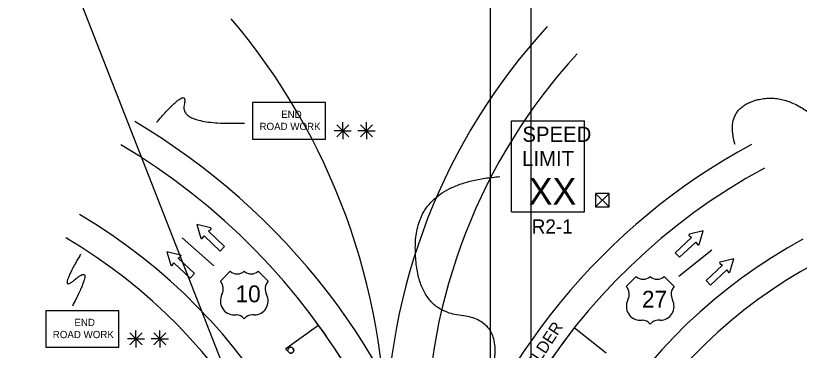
# Model space of a CAD drawing. Extents: x 16715 to 19504, y 7040 to 8495.
# Drawn here: x 16714.6 to 17178.6, y 7997.5 to 8196 of the extents above; entities that cross this region are included whole.
import ezdxf

# ---------------------------------------------------------------- set-up
doc = ezdxf.new("R2010")
doc.units = 0
for name, color, linetype in [('ALI_LEGAL_EX', 7, 'Continuous'), ('MT_SCRATCH_LEVEL_A', 7, 'Continuous'), ('MT_SCRATCH_LEVEL_E', 7, 'Continuous'), ('PAVT_EDGE_EX', 7, 'Continuous'), ('TRAFFIC_SIGNS_PR', 7, 'Continuous'), ('TYPICAL_EX', 7, 'Continuous'), ('TYPICAL_TEXT_DIMEN_PR', 7, 'Continuous')]:
    doc.layers.add(name, color=color, linetype=linetype)

msp = doc.modelspace()

# ---------------------------------------------------------------- linework, layer by layer
at = {"layer": 'ALI_LEGAL_EX'}
for p, q in [((16714.57, 8302.79), (16936.6, 7734.43)), ((16995.53, 8241.3), (16995.53, 7423.16)), ((17019.53, 8241.3), (17019.53, 7423.16))]:
    msp.add_line(p, q, dxfattribs=at)
for points in [[(16831.92, 8047.71), (16813.25, 8064.33)], [(17107.31, 8041.46), (17126.77, 8057.16)]]:
    msp.add_lwpolyline(points, dxfattribs=at)
for centre, radius, start, end in [((16545.79, 7943.78), 388, 0, 40.1908), ((17297.79, 7943.78), 364, 137.516, 180), ((17297.79, 7943.78), 340, 137.516, 180)]:
    msp.add_arc(centre, radius, start, end, dxfattribs=at)
at = {"layer": 'MT_SCRATCH_LEVEL_A'}
for points in [[(16893.99, 8012.41), (16874.52, 7998.38)], [(17064.2, 7995.96), (17045.35, 8010.82)], [(16875.01, 7997.69), (16875.7, 7997.68)]]:
    msp.add_lwpolyline(points, dxfattribs=at)
for centre, radius, start, end in [((16579.24, 7785.52), 388, 22.8554, 35.7873), ((17331.24, 7785.52), 364, 141.7598, 180), ((16579.24, 7785.52), 364, 35.6537, 35.7873), ((16877.5, 7997.65), 1.8, 0, 179.0978), ((16877.5, 7997.65), 1.8, 250.5205, 0)]:
    msp.add_arc(centre, radius, start, end, dxfattribs=at)
at = {"layer": 'MT_SCRATCH_LEVEL_E'}
for p, q in [((16829.97, 8070.13), (16821.86, 8072.1)), ((16821.86, 8072.1), (16824.29, 8064.14)), ((16825.12, 8064.02), (16826.11, 8065.52)), ((16826.11, 8065.52), (16835.74, 8056.41)), ((16828.69, 8068.24), (16830.14, 8069.32)), ((16838.31, 8059.12), (16828.69, 8068.24)), ((17113.39, 8065.58), (17114.83, 8064.5)), ((17121.65, 8068.35), (17113.56, 8066.4)), ((17119.21, 8060.38), (17121.65, 8068.35)), ((17114.83, 8064.5), (17105.16, 8055.43)), ((17107.72, 8052.7), (17117.39, 8061.77)), ((17117.39, 8061.77), (17118.38, 8060.26)), ((16812.15, 8054.06), (16804.04, 8056.02)), ((16804.04, 8056.02), (16806.47, 8048.06)), ((16835.74, 8056.41), (16838.31, 8059.12)), ((16810.87, 8052.16), (16812.32, 8053.24)), ((16820.49, 8043.05), (16810.87, 8052.16)), ((17105.16, 8055.43), (17107.72, 8052.7)), ((17139.85, 8051.88), (17131.76, 8049.93)), ((17137.41, 8043.91), (17139.85, 8051.88)), ((16807.3, 8047.94), (16808.29, 8049.45)), ((16808.29, 8049.45), (16817.92, 8040.33)), ((17133.03, 8048.03), (17123.37, 8038.96)), ((17131.59, 8049.11), (17133.03, 8048.03)), ((16817.92, 8040.33), (16820.49, 8043.05)), ((17125.92, 8036.23), (17135.6, 8045.3)), ((17135.6, 8045.3), (17136.58, 8043.79)), ((17123.37, 8038.96), (17125.92, 8036.23))]:
    msp.add_line(p, q, dxfattribs=at)
for centre, start, end in [((16829.85, 8069.68), 306.594, 76.331), ((17113.67, 8065.95), 103.5821, 233.121), ((16824.73, 8064.28), 196.9827, 326.5217), ((17118.76, 8060.52), 213.1934, 342.9303), ((16812.03, 8053.6), 306.594, 76.331), ((16806.92, 8048.2), 196.9827, 326.5217), ((17131.87, 8049.48), 103.5821, 233.121), ((17136.96, 8044.05), 213.1934, 342.9303)]:
    msp.add_arc(centre, 0.463, start, end, dxfattribs=at)
at = {"layer": 'PAVT_EDGE_EX'}
for centre, radius, start, end in [((16579.24, 7785.52), 404, 15.917, 59.3713), ((16579.24, 7785.52), 388, 0, 59.3713), ((17331.24, 7785.52), 380, 118.4372, 163.0483), ((17331.24, 7785.52), 364, 118.4372, 180), ((16579.24, 7785.52), 340, 0, 59.3713), ((16579.24, 7785.52), 324, 0, 59.3713), ((17331.24, 7785.52), 316, 118.4372, 180), ((17331.24, 7785.52), 300, 118.4372, 180)]:
    msp.add_arc(centre, radius, start, end, dxfattribs=at)
at = {"layer": 'TRAFFIC_SIGNS_PR'}
for p, q in [((17008.13, 8133.7), (17051.33, 8133.7)), ((17008.13, 8079.7), (17008.13, 8133.7)), ((17051.33, 8079.7), (17051.33, 8133.7)), ((17008.13, 8079.7), (17051.33, 8079.7))]:
    msp.add_line(p, q, dxfattribs=at)
for points in [[(16854.89, 8122.83), (16898.09, 8122.83), (16898.09, 8144.43), (16854.89, 8144.43)], [(16732.47, 7999.45), (16775.67, 7999.45), (16775.67, 8021.05), (16732.47, 8021.05)]]:
    msp.add_lwpolyline(points, close=True, dxfattribs=at)
msp.add_circle((16877.5, 7997.65), 1.8, dxfattribs=at)
at = {"layer": 'TYPICAL_EX'}
for p, q in [((16835.78, 8038.61), (16841.67, 8044.51)), ((16864.07, 8038.61), (16858.18, 8044.51)), ((17076.15, 8035.43), (17082.04, 8041.32)), ((17104.44, 8035.43), (17098.55, 8041.32)), ((16844.02, 8018.55), (16845.2, 8018.55)), ((16855.83, 8018.55), (16854.65, 8018.55)), ((17084.39, 8015.37), (17085.57, 8015.37)), ((17096.2, 8015.37), (17095.02, 8015.37))]:
    msp.add_line(p, q, dxfattribs=at)
for centre, radius, start, end in [((16845.8, 8048.8), 5.96, 226.1404, 313.8596), ((16854.05, 8048.8), 5.96, 226.1404, 313.8596), ((16830.19, 8033.89), 7.31, 333.0977, 40.1936), ((16869.66, 8033.89), 7.31, 139.8064, 206.9023), ((17086.17, 8045.62), 5.96, 226.1404, 313.8596), ((17094.42, 8045.62), 5.96, 226.1404, 313.8596), ((17070.56, 8030.71), 7.31, 333.0977, 40.1936), ((17110.03, 8030.71), 7.31, 139.8064, 206.9023), ((16844.03, 8026.8), 8.24, 152.6698, 269.9013), ((16855.81, 8026.8), 8.24, 270.0987, 27.3302), ((17084.4, 8023.61), 8.24, 152.6698, 269.9013), ((17096.18, 8023.61), 8.24, 270.0987, 27.3302), ((16845.21, 8012.65), 5.91, 37.1038, 90.1385), ((16854.63, 8012.65), 5.91, 89.8615, 142.8962), ((17085.58, 8009.46), 5.91, 37.1038, 90.1385), ((17095, 8009.46), 5.91, 89.8615, 142.8962)]:
    msp.add_arc(centre, radius, start, end, dxfattribs=at)
at = {"layer": 'TYPICAL_TEXT_DIMEN_PR'}
for p, q in [((16911.83, 8131.33), (16904.65, 8124.16)), ((16904.66, 8131.33), (16911.83, 8124.16)), ((16908.24, 8127.75), (16908.24, 8132.76)), ((16918.78, 8131.33), (16925.95, 8124.16)), ((16925.95, 8131.33), (16918.78, 8124.16)), ((16922.37, 8127.75), (16922.37, 8132.76)), ((16908.24, 8127.75), (16903.14, 8127.75)), ((16908.24, 8127.75), (16911.83, 8127.75)), ((16908.24, 8127.75), (16913.28, 8127.75)), ((16908.24, 8127.75), (16908.24, 8122.68)), ((16922.37, 8127.75), (16917.27, 8127.75)), ((16922.37, 8127.75), (16925.95, 8127.75)), ((16922.37, 8127.75), (16927.4, 8127.75)), ((16922.37, 8127.75), (16922.37, 8122.68)), ((17058, 8090.59), (17066, 8082.59)), ((17058, 8082.59), (17066, 8090.59)), ((16785.82, 8004.37), (16785.82, 8009.38)), ((16799.95, 8004.37), (16799.95, 8009.38)), ((16782.24, 8007.95), (16789.41, 8000.78)), ((16789.41, 8007.95), (16782.24, 8000.78)), ((16796.36, 8007.95), (16803.53, 8000.78)), ((16803.53, 8007.95), (16796.36, 8000.78)), ((16785.82, 8004.37), (16780.72, 8004.37)), ((16785.82, 8004.37), (16789.41, 8004.37)), ((16785.82, 8004.37), (16790.86, 8004.37)), ((16785.82, 8004.37), (16785.82, 7999.3)), ((16799.95, 8004.37), (16794.85, 8004.37)), ((16799.95, 8004.37), (16803.53, 8004.37)), ((16799.95, 8004.37), (16804.99, 8004.37)), ((16799.95, 8004.37), (16799.95, 7999.3))]:
    msp.add_line(p, q, dxfattribs=at)
msp.add_lwpolyline([(17058, 8090.59), (17058, 8082.59), (17066, 8082.59), (17066, 8090.59)], close=True, dxfattribs=at)
for points in [[(16798.01, 8132.61), (16817.22, 8155.22), (16811.38, 8130.94), (16850.07, 8132.34)], [(17140.6, 8119.52), (17134.59, 8139.51), (17167.51, 8151.04), (17201.36, 8125.68), (17195.57, 8073.25), (17244.37, 8077.78)], [(16958.07, 7946.57), (16989.43, 7956), (17004.37, 8015.48), (16951.17, 8021.19), (16951.27, 8096.95), (17001.2, 8100.55)], [(16753.03, 8054.57), (16738.57, 8029.95), (16761.78, 8049.8), (16748.13, 8023.79)]]:
    msp.add_open_spline(points, degree=2, dxfattribs=at)

# ---------------------------------------------------------------- texts
at = {"layer": 'TRAFFIC_SIGNS_PR'}
for s, height, p in [('END', 4.31, (16871.77, 8135.35)), ('ROAD WORK', 4.31, (16858.95, 8128.16)), ('SPEED', 9, (17014.62, 8121.17)), ('LIMIT', 9, (17014.44, 8106.77)), ('XX', 15.785, (17018.39, 8083.93)), ('R2-1', 8.37, (17020.14, 8066.83)), ('END', 4.31, (16749.35, 8011.97)), ('ROAD WORK', 4.31, (16736.53, 8004.78))]:
    msp.add_text(s, height=height, dxfattribs=at).set_placement(p)
at = {"layer": 'TYPICAL_EX'}
for s, p in [('10', (16844.77, 8026.04)), ('27', (17085.4, 8022.86))]:
    msp.add_text(s, height=10, dxfattribs=at).set_placement(p)
at = {"layer": 'TYPICAL_TEXT_DIMEN_PR'}
msp.add_text('SHOULDER', height=7, rotation=56.8597, dxfattribs=at).set_placement((17010.54, 7967.98))

doc.saveas('drawing.dxf')
